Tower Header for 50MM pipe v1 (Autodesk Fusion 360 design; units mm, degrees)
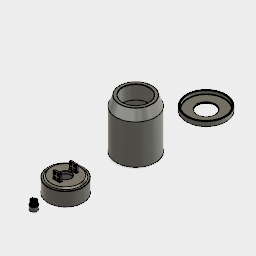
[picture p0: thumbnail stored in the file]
part number: Slipring stress relief
form "Form1"
cylinder_primitive "CylinderPrimitive4" Height 50 Diameter 56
hole "Hole3" HoleDepth 50 HoleDiameter 50 TipAngle 118
cylinder_primitive "CylinderPrimitive5" Height 20 Diameter 56
hole "Hole4" HoleDepth 50 HoleDiameter 37 TipAngle 118
chamfer "Chamfer10" distance 0.5
chamfer "Chamfer11" distance 0.5
chamfer "Chamfer12" distance 0.5
chamfer "Chamfer13" distance 1
chamfer "Chamfer14" distance 0.5
chamfer "Chamfer15" distance 5
draft "Draft2" Draft -25 Draft 0
chamfer "Chamfer16" distance 0.25
cylinder_primitive "CylinderPrimitive14" Height 7 Diameter 56
cylinder_primitive "CylinderPrimitive15" Height -10 Diameter 25
cylinder_primitive "CylinderPrimitive16" Height -5 Diameter 52
chamfer "Chamfer28" distance 0.5
chamfer "Chamfer29" distance 0.5
chamfer "Chamfer30" distance 0.5
chamfer "Chamfer31" distance 0.5
chamfer "Chamfer32" distance 0.5
chamfer "Chamfer33" distance 0.5
cylinder_primitive "CylinderPrimitive18" Height 20 Diameter 50
cylinder_primitive "CylinderPrimitive19" Height 10 Diameter 43.5
cylinder_primitive "CylinderPrimitive20" Height -8 Diameter 38
cylinder_primitive "CylinderPrimitive21" Height -18 Diameter 44.93
cylinder_primitive "CylinderPrimitive22" Height -18 Diameter 15
box_primitive "BoxPrimitive1" DistanceX 3 DistanceY 10 DistanceZ 10 OffsetDistanceX 0 OffsetDistanceY 0
box_primitive "BoxPrimitive2" DistanceX 3 DistanceY 10 DistanceZ 10 OffsetDistanceX 0 OffsetDistanceY 0
cylinder_primitive "CylinderPrimitive23" Height -5 Diameter 2
cylinder_primitive "CylinderPrimitive24" Height -5 Diameter 2
cylinder_primitive "CylinderPrimitive25" Height -5 Diameter 2
cylinder_primitive "CylinderPrimitive26" Height -5 Diameter 2
cylinder_primitive "CylinderPrimitive27" Height -5 Diameter 2
cylinder_primitive "CylinderPrimitive28" Height -5 Diameter 2
cylinder_primitive "CylinderPrimitive29" Height -5 Diameter 2
cylinder_primitive "CylinderPrimitive30" Height -5 Diameter 2
chamfer "Chamfer34" distance 0.5
chamfer "Chamfer35" distance 0.5
chamfer "Chamfer36" distance 0.5
chamfer "Chamfer37" distance 0.5
chamfer "Chamfer39" distance 0.5
chamfer "Chamfer40" distance 0.5
chamfer "Chamfer41" distance 0.5
chamfer "Chamfer42" distance 10
component_from_bodies "Body->Comp2"
component_from_bodies "Body->Comp3"
component_from_bodies "Body->Comp4"
cylinder_primitive "CylinderPrimitive31" Height 6 Diameter 10
cylinder_primitive "CylinderPrimitive32" Height -3 Diameter 5
cylinder_primitive "CylinderPrimitive33" Height -8 Diameter 4
step "MoveBody1"
step "MoveBody2"
box_primitive "BoxPrimitive3" DistanceX 4 DistanceY 1.5 DistanceZ 6 OffsetDistanceX 0 OffsetDistanceY 0
box_primitive "BoxPrimitive4" DistanceX 4 DistanceY 1.5 DistanceZ 6 OffsetDistanceX 0 OffsetDistanceY 0
box_primitive "BoxPrimitive5" DistanceX 1.5 DistanceY 4 DistanceZ 6 OffsetDistanceX 0 OffsetDistanceY 0
box_primitive "BoxPrimitive6" DistanceX 1.5 DistanceY 4 DistanceZ 6 OffsetDistanceX 0 OffsetDistanceY 0
cylinder_primitive "CylinderPrimitive34" Height -18 Diameter 2
cylinder_primitive "CylinderPrimitive35" Height -18 Diameter 2
cylinder_primitive "CylinderPrimitive36" Height -18 Diameter 2
cylinder_primitive "CylinderPrimitive37" Height -18 Diameter 2
chamfer "Chamfer43" distance 0.25
chamfer "Chamfer44" distance 0.25
chamfer "Chamfer45" distance 0.25
chamfer "Chamfer46" distance 0.25
chamfer "Chamfer47" distance 0.25
chamfer "Chamfer48" distance 0.1
component_from_bodies "Body->Comp5"
delete_face "DeleteFace1"
delete_face "DeleteFace2"
delete_face "DeleteFace3"
delete_face "DeleteFace4"
step "MoveBody1"
step "MoveBody1"
step "MoveBody1"
step "MoveBody2"
step "MoveBody2"
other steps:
base_feature "Base Feature1"
base_feature "Base Feature1"
base_feature "Base Feature1"
base_feature "Base Feature1"
create_component "CreateComponent2"
remove_body "RemoveBody2"
create_component "CreateComponent3"
remove_body "RemoveBody3"
create_component "CreateComponent4"
remove_body "RemoveBody4"
create_component "CreateComponent5"
remove_body "RemoveBody5"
